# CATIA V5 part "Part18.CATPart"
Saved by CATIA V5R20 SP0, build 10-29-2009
Part number: Parallel Pin Unhardened_DIN_Parallel Pin ISO 2338 - 2 h6 x 10 - St
Revision: ANY
Definition: UNKNOWN
Nomenclature: Parallel Pin Unhardened_DIN_Parallel Pin ISO 2338 - 2 h6 x 10 - St
Source: Unknown
Bounding box of the stored display mesh (mm): x 0 to 10, y -1 to 1, z -1 to 1
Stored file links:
  C:\Users\Utente\Desktop\IO LAVORO\3D X SITO CF\CUMSA\3D files BA\BA 122024\Part18.CATPart
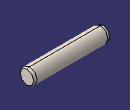
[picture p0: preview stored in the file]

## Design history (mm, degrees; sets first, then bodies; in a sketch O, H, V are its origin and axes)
Body1 "Base-Revolve" (main body)
  Solid1: solid without history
